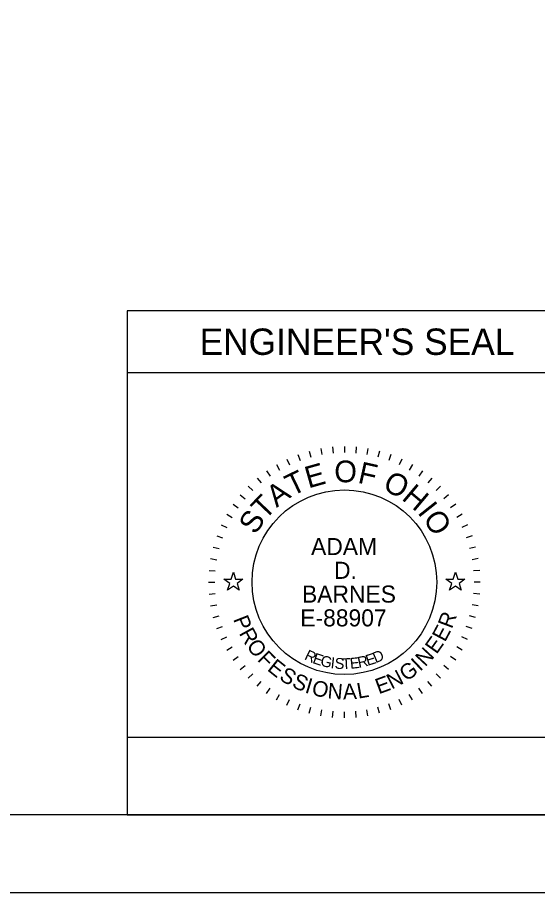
# Model space of a CAD drawing. Extents: x 0 to 34, y 0 to 22.
# Drawn here: x 6.64 to 9.99, y 0 to 5.64 of the extents above; entities that cross this region are included whole.
import ezdxf

# ---------------------------------------------------------------- set-up
doc = ezdxf.new("R2010")
doc.units = 0
for name, color, linetype in [('Default', 7, 'Continuous'), ('SH_Border', 7, 'Continuous'), ('SH_Cut_Line', 7, 'Continuous'), ('SH_Data', 7, 'Continuous')]:
    doc.layers.add(name, color=color, linetype=linetype)

msp = doc.modelspace()

# ---------------------------------------------------------------- linework, layer by layer
at = {"layer": 'Default'}
for points in [[(7.9736, 2.02), (8.0205, 2.02), (8.035, 2.0645), (8.0495, 2.02), (8.0964, 2.02), (8.0585, 1.9924), (8.073, 1.9478), (8.035, 1.9754), (7.997, 1.9478), (8.0115, 1.9924)], [(9.4036, 2.02), (9.4505, 2.02), (9.465, 2.0645), (9.4795, 2.02), (9.5264, 2.02), (9.4885, 1.9924), (9.503, 1.9478), (9.465, 1.9754), (9.427, 1.9478), (9.4415, 1.9924)]]:
    msp.add_lwpolyline(points, close=True, dxfattribs=at)
at = {"layer": 'SH_Border'}
msp.add_lwpolyline([(1.5, 21.5), (33.5, 21.5), (33.5, 0.5), (1.5, 0.5)], close=True, dxfattribs=at)
at = {"layer": 'SH_Cut_Line'}
msp.add_lwpolyline([(0, 0), (34, 0), (34, 22), (0, 22)], close=True, dxfattribs=at)
at = {"layer": 'SH_Data'}
for p, q in [((10.15, 3.75), (7.35, 3.75)), ((7.35, 3.75), (7.35, 0.5)), ((10.15, 3.35), (7.35, 3.35)), ((8.4507, 2.8222), (8.4644, 2.7846)), ((8.5235, 2.8452), (8.5339, 2.8065)), ((8.5981, 2.8617), (8.605, 2.8223)), ((8.6737, 2.8717), (8.6772, 2.8318)), ((8.75, 2.875), (8.75, 2.835)), ((8.8263, 2.8717), (8.8228, 2.8318)), ((8.9019, 2.8617), (8.895, 2.8223)), ((8.9765, 2.8452), (8.9661, 2.8065)), ((9.0493, 2.8222), (9.0356, 2.7846)), ((8.3802, 2.793), (8.3971, 2.7568)), ((9.1198, 2.793), (9.1029, 2.7568)), ((8.2481, 2.7168), (8.2711, 2.684)), ((8.3125, 2.7578), (8.3325, 2.7231)), ((9.1875, 2.7578), (9.1675, 2.7231)), ((9.2519, 2.7168), (9.2289, 2.684)), ((8.1876, 2.6703), (8.2133, 2.6396)), ((9.3124, 2.6703), (9.2867, 2.6396)), ((8.1313, 2.6187), (8.1596, 2.5904)), ((9.3687, 2.6187), (9.3404, 2.5904)), ((8.0797, 2.5624), (8.1104, 2.5367)), ((9.4203, 2.5624), (9.3896, 2.5367)), ((8.0332, 2.5019), (8.066, 2.4789)), ((9.4668, 2.5019), (9.434, 2.4789)), ((7.9922, 2.4375), (8.0269, 2.4175)), ((9.5078, 2.4375), (9.4731, 2.4175)), ((7.957, 2.3698), (7.9932, 2.3529)), ((9.543, 2.3698), (9.5068, 2.3529)), ((7.9278, 2.2993), (7.9654, 2.2856)), ((9.5722, 2.2993), (9.5346, 2.2856)), ((7.9048, 2.2265), (7.9435, 2.2161)), ((9.5952, 2.2265), (9.5565, 2.2161)), ((7.8883, 2.1519), (7.9277, 2.145)), ((9.6117, 2.1519), (9.5723, 2.145)), ((7.8783, 2.0763), (7.9182, 2.0728)), ((9.6217, 2.0763), (9.5818, 2.0728)), ((7.875, 2), (7.915, 2)), ((9.625, 2), (9.585, 2)), ((7.8783, 1.9237), (7.9182, 1.9272)), ((9.6217, 1.9237), (9.5818, 1.9272)), ((7.8883, 1.8481), (7.9277, 1.855)), ((9.6117, 1.8481), (9.5723, 1.855)), ((7.9048, 1.7735), (7.9435, 1.7839)), ((9.5952, 1.7735), (9.5565, 1.7839)), ((7.9278, 1.7007), (7.9654, 1.7144)), ((9.5722, 1.7007), (9.5346, 1.7144)), ((7.957, 1.6302), (7.9932, 1.6471)), ((9.543, 1.6302), (9.5068, 1.6471)), ((7.9922, 1.5625), (8.0269, 1.5825)), ((9.5078, 1.5625), (9.4731, 1.5825)), ((8.0332, 1.4981), (8.066, 1.5211)), ((9.4668, 1.4981), (9.434, 1.5211)), ((8.0797, 1.4376), (8.1104, 1.4633)), ((9.4203, 1.4376), (9.3896, 1.4633)), ((8.1313, 1.3813), (8.1596, 1.4096)), ((8.1876, 1.3297), (8.2133, 1.3604)), ((9.3124, 1.3297), (9.2867, 1.3604)), ((9.3687, 1.3813), (9.3404, 1.4096)), ((8.2481, 1.2832), (8.2711, 1.316)), ((9.2519, 1.2832), (9.2289, 1.316)), ((8.3125, 1.2422), (8.3325, 1.2769)), ((8.3802, 1.207), (8.3971, 1.2432)), ((9.1198, 1.207), (9.1029, 1.2432)), ((9.1875, 1.2422), (9.1675, 1.2769)), ((8.4507, 1.1778), (8.4644, 1.2154)), ((8.5235, 1.1548), (8.5339, 1.1935)), ((8.9765, 1.1548), (8.9661, 1.1935)), ((9.0493, 1.1778), (9.0356, 1.2154)), ((8.5981, 1.1383), (8.605, 1.1777)), ((8.6737, 1.1283), (8.6772, 1.1682)), ((8.75, 1.125), (8.75, 1.165)), ((8.8263, 1.1283), (8.8228, 1.1682)), ((8.9019, 1.1383), (8.895, 1.1777)), ((10.15, 0.5), (7.35, 0.5))]:
    msp.add_line(p, q, dxfattribs=at)
msp.add_lwpolyline([(10.15, 0.5), (10.15, 1), (7.35, 1), (7.35, 0.5)], close=True, dxfattribs=at)
msp.add_circle((8.75, 2), 0.595, dxfattribs=at)

# ---------------------------------------------------------------- texts
for s, height, p in [("ENGINEER'S SEAL", 0.17, (7.8176, 3.465)), ('ADAM', 0.11, (8.5353, 2.1749)), ('D.', 0.11, (8.6832, 2.0216)), ('BARNES', 0.11, (8.477, 1.8684)), ('E-88907', 0.11, (8.4659, 1.7151))]:
    msp.add_text(s, height=height, dxfattribs=at).set_placement(p)
for s, height, rotation, p in [('E', 0.14, 15.7571, (8.5184, 2.6038)), ('O', 0.14, 359.7812, (8.6847, 2.6443)), ('F', 0.14, 347.4362, (8.8311, 2.6417)), ('T', 0.14, 25.7167, (8.4116, 2.5518)), ('O', 0.14, 332.2586, (8.9898, 2.6015)), ('A', 0.14, 36.4747, (8.3134, 2.4781)), ('H', 0.14, 319.9136, (9.1132, 2.5361)), ('T', 0.14, 46.4344, (8.2383, 2.3964)), ('I', 0.14, 308.367, (9.2165, 2.4483)), ('S', 0.14, 57.1924, (8.1781, 2.3014)), ('O', 0.14, 303.1491, (9.2521, 2.4089)), ('R', 0.1, 69.2322, (9.4419, 1.6954)), ('P', 0.1, 291.494, (8.0323, 1.7621)), ('R', 0.1, 298.7311, (8.069, 1.6717)), ('E', 0.1, 61.9951, (9.3976, 1.6098)), ('E', 0.1, 54.758, (9.3433, 1.5314)), ('O', 0.1, 306.4666, (8.1155, 1.5883)), ('N', 0.1, 47.0224, (9.2702, 1.4508)), ('F', 0.1, 314.7068, (8.1843, 1.4983)), ('R', 0.07, 334.487, (8.4875, 1.5051)), ('E', 0.07, 341.04, (8.5406, 1.4801)), ('G', 0.07, 347.4752, (8.5914, 1.4618)), ('R', 0.07, 11.9184, (8.8425, 1.4474)), ('E', 0.07, 17.6836, (8.8998, 1.4602)), ('D', 0.07, 23.3052, (8.951, 1.477)), ('E', 0.1, 321.4393, (8.2478, 1.4348)), ('I', 0.07, 353.7858, (8.6591, 1.4468)), ('S', 0.07, 356.8926, (8.6858, 1.4429)), ('T', 0.07, 3.0061, (8.7357, 1.4387)), ('E', 0.07, 6.0117, (8.7889, 1.4412)), ('G', 0.1, 35.0469, (9.1481, 1.357)), ('I', 0.1, 43.287, (9.2368, 1.4214)), ('S', 0.1, 328.6764, (8.3243, 1.3752)), ('N', 0.1, 27.3113, (9.0545, 1.3075)), ('S', 0.1, 335.9134, (8.4064, 1.3266)), ('I', 0.1, 343.1505, (8.4906, 1.2897)), ('O', 0.1, 346.8859, (8.5339, 1.2751)), ('E', 0.1, 20.0742, (8.9712, 1.277)), ('N', 0.1, 355.1261, (8.6388, 1.2517)), ('A', 0.1, 2.8617, (8.7423, 1.2437)), ('L', 0.1, 10.0987, (8.8394, 1.249))]:
    msp.add_text(s, height=height, rotation=rotation, dxfattribs=at).set_placement(p)

doc.saveas('drawing.dxf')
